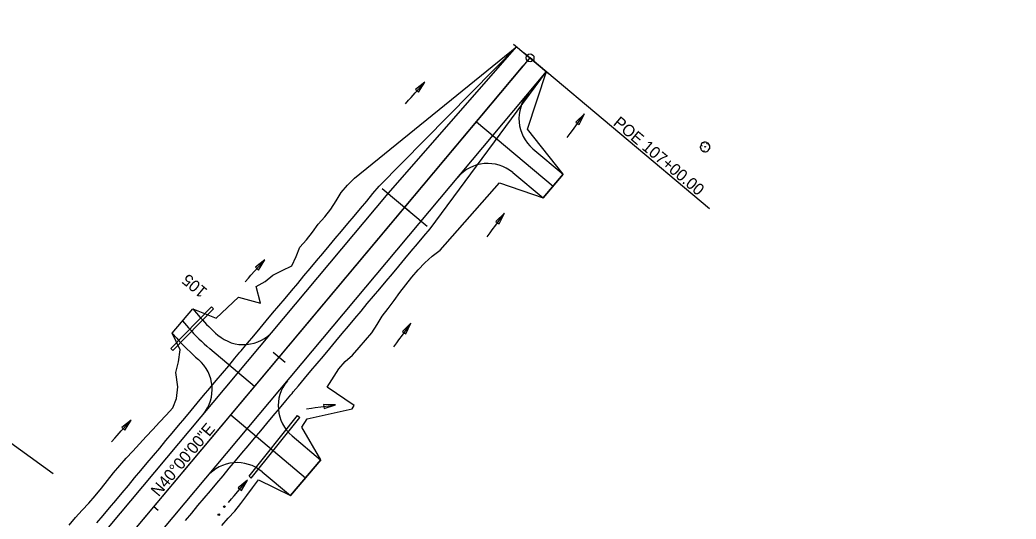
# Model space of a CAD drawing. Extents: x 1 to 1477871, y 1 to 1872901.
# Drawn here: x 1444024 to 1444534, y 1855060 to 1855316 of the extents above; entities that cross this region are included whole.
import ezdxf

# ---------------------------------------------------------------- set-up
doc = ezdxf.new("R2010")
doc.units = 0
for name, color, linetype in [('R_Drive', 7, 'Continuous'), ('R_Floodplain', 7, 'Continuous'), ('R_Horz Alg', 7, 'Continuous'), ('R_Horz Alg Annot', 7, 'Continuous'), ('R_No Plot', 7, 'Continuous'), ('R_Proposed Const Limits_Cut', 7, 'Continuous'), ('R_Proposed Const Limits_Fill', 7, 'Continuous'), ('R_Proposed Road_Lane', 7, 'Continuous'), ('R_Proposed Road_Shoulder', 7, 'Continuous'), ('R_Temp Easement', 7, 'Continuous'), ('R_Water', 7, 'Continuous'), ('S_TREE', 7, 'Continuous')]:
    doc.layers.add(name, color=color, linetype=linetype)

msp = doc.modelspace()

# ---------------------------------------------------------------- linework, layer by layer
at = {"layer": 'R_Drive'}
for p, q in [((1444286.64, 1855249.88), (1444302.16, 1855236.85)), ((1444276.36, 1855237.62), (1444291.84, 1855224.63)), ((1444302.2, 1855236.82), (1444291.84, 1855224.63)), ((1444101.85, 1855155.5), (1444112.32, 1855167.83)), ((1444112.32, 1855167.83), (1444116.19, 1855163.41)), ((1444101.85, 1855155.5), (1444104.16, 1855152.87)), ((1444163.28, 1855102.86), (1444177.88, 1855090.61)), ((1444177.94, 1855090.56), (1444162.4, 1855072.27)), ((1444147.86, 1855084.48), (1444162.4, 1855072.27))]:
    msp.add_line(p, q, dxfattribs=at)
for centre, radius, start, end in [((1444299.5, 1855265.2), 20, 140, 230), ((1444263.5, 1855222.3), 20, 50, 140), ((1444185.37, 1855224.07), 92, 221.2436, 229.1945), ((1444138.32, 1855169.57), 20, 229.1945, 320), ((1444185.37, 1855224.07), 108, 221.2436, 229.5469), ((1444102.32, 1855126.67), 20, 320, 49.5469), ((1444176.14, 1855118.18), 20, 140, 230), ((1444135, 1855069.16), 20, 50, 140)]:
    msp.add_arc(centre, radius, start, end, dxfattribs=at)
at = {"layer": 'R_Floodplain'}
msp.add_open_spline([(1444534.23, 1857777.84), (1444398.78, 1857609.12), (1444367.89, 1857131.47), (1444306.1, 1856808.28), (1444134.95, 1856378.26), (1444024.62, 1856227.92), (1443837.91, 1855964.82), (1443664.53, 1855852.06), (1443479.03, 1855867.82), (1443335.96, 1855886.01), (1443298.37, 1855854.49), (1443356.57, 1855756.28), (1443606.51, 1855482.27), (1443757.19, 1855307.33), (1443863.11, 1855113.58), (1443878.59, 1855007.91), (1443849.87, 1854910.07), (1443760.66, 1854753.08), (1443429.28, 1854512.04), (1443240.87, 1854371.16), (1443115.26, 1854254.04), (1443060.94, 1853889.1), (1443099.99, 1853680.31), (1443032.09, 1853386.66), (1443001.54, 1853198.25), (1444534.23, 1857777.84), (1443001.54, 1853198.25)], degree=3, dxfattribs=at)
at = {"layer": 'R_Horz Alg'}
for q in [(1444285.2, 1855296.38), (1444281.71, 1855292.23)]:
    msp.add_line((1444054.15, 1855021.02), q, dxfattribs=at)
at = {"layer": 'R_Horz Alg Annot'}
for points in [[(1444282.13, 1855298.95), (1444288.26, 1855293.81)], [(1444287.49, 1855294.45), (1444285.2, 1855296.38)], [(1444285.2, 1855296.38), (1444377.12, 1855219.25)], [(1444223.21, 1855217.85), (1444220.92, 1855219.78)], [(1444153.57, 1855145.74), (1444159.7, 1855140.6)], [(1444094.66, 1855064.64), (1444092.36, 1855066.57)]]:
    msp.add_lwpolyline(points, dxfattribs=at)
msp.add_circle((1444285.2, 1855296.38), 2, dxfattribs=at)
at = {"layer": 'R_No Plot'}
for p, q in [((1444276.77, 1855303.45), (1444294.69, 1855288.41)), ((1444257.75, 1855263.67), (1444297.02, 1855230.73)), ((1444209.43, 1855229.42), (1444232.41, 1855210.13)), ((1444107.09, 1855161.67), (1444110.18, 1855158.14)), ((1444144.06, 1855128.19), (1444121.09, 1855147.46)), ((1444131.82, 1855113.6), (1444170.17, 1855081.42))]:
    msp.add_line(p, q, dxfattribs=at)
msp.add_arc((1444185.37, 1855224.07), 100, 221.2436, 230, dxfattribs=at)
at = {"layer": 'R_Proposed Const Limits_Cut'}
for points in [[(1444112.32, 1855167.83), (1444124.29, 1855163.04), (1444135.72, 1855173.78), (1444147.11, 1855170.75), (1444144.76, 1855179.25), (1444149.49, 1855181.8), (1444153.3, 1855185.13), (1444158.22, 1855187.53), (1444163.17, 1855189.9), (1444165.33, 1855194.62), (1444167.24, 1855199.54), (1444170.62, 1855203.24), (1444173.68, 1855207.2), (1444176.6, 1855211.27), (1444179.99, 1855214.95), (1444183.14, 1855218.84), (1444185.78, 1855223.15), (1444188.45, 1855227.44), (1444191.68, 1855231.26), (1444195.24, 1855234.8), (1444278.35, 1855302.12)], [(1444195.05, 1855118.37), (1444181.28, 1855127.74), (1444187.14, 1855137.15), (1444190.52, 1855140.85), (1444194.26, 1855144.24), (1444197.54, 1855148.01), (1444200.81, 1855151.79), (1444204.06, 1855155.59), (1444206.78, 1855159.84), (1444209.48, 1855164.1), (1444212.53, 1855168.07), (1444215.48, 1855172.12), (1444218.43, 1855176.17), (1444221.53, 1855180.1), (1444224.55, 1855184.09), (1444227.85, 1855187.85), (1444231.32, 1855191.47), (1444235.06, 1855194.86), (1444239.2, 1855197.91), (1444269.48, 1855232.31), (1444291.84, 1855224.63), (1444302.2, 1855236.82), (1444283.94, 1855259.79), (1444293.62, 1855289.31)], [(1444102.11, 1855117.13), (1444104.09, 1855121.99), (1444104.7, 1855128.01), (1444103.75, 1855135.33), (1444105.08, 1855140.75), (1444105.86, 1855146.87), (1444101.85, 1855155.5)], [(1444127.17, 1855056.93), (1444130.5, 1855060.67), (1444133.88, 1855064.36), (1444137.04, 1855068.24), (1444140.03, 1855072.26), (1444143.02, 1855076.27), (1444146.01, 1855080.29), (1444162.4, 1855072.27), (1444177.94, 1855090.56), (1444168.24, 1855107.33), (1444170.99, 1855111.54), (1444193.99, 1855116.63), (1444195.05, 1855118.37)]]:
    msp.add_lwpolyline(points, dxfattribs=at)
at = {"layer": 'R_Proposed Const Limits_Fill'}
msp.add_lwpolyline([(1444049.04, 1855057.22), (1444052.28, 1855061.03), (1444055.65, 1855064.74), (1444059.08, 1855068.38), (1444062.38, 1855072.14), (1444065.51, 1855076.04), (1444068.63, 1855079.95), (1444071.75, 1855083.86), (1444074.98, 1855087.68), (1444078.27, 1855091.44), (1444081.72, 1855095.08), (1444085.09, 1855098.77), (1444088.46, 1855102.48), (1444091.85, 1855106.15), (1444095.27, 1855109.81), (1444098.68, 1855113.48), (1444102.11, 1855117.13)], dxfattribs=at)
at = {"layer": 'R_Proposed Road_Lane'}
for p, q in [((1444212.49, 1855226.85), (1444278.35, 1855302.12)), ((1444062.57, 1855013.95), (1444293.62, 1855289.31)), ((1444045.72, 1855028.1), (1444212.49, 1855226.85))]:
    msp.add_line(p, q, dxfattribs=at)
at = {"layer": 'R_Proposed Road_Shoulder'}
for p, q in [((1444207.89, 1855230.7), (1444278.35, 1855302.12)), ((1444233.94, 1855208.85), (1444293.62, 1855289.31))]:
    msp.add_line(p, q, dxfattribs=at)
for points in [[(1444063.27, 1855058.34), (1444066.48, 1855062.17), (1444069.69, 1855066), (1444072.91, 1855069.83), (1444076.12, 1855073.66), (1444079.34, 1855077.49), (1444082.55, 1855081.32), (1444085.76, 1855085.15), (1444088.98, 1855088.98), (1444092.19, 1855092.81), (1444095.41, 1855096.64), (1444098.62, 1855100.47), (1444101.83, 1855104.31), (1444105.05, 1855108.14), (1444108.26, 1855111.97), (1444111.48, 1855115.8), (1444114.69, 1855119.63), (1444117.9, 1855123.46), (1444121.12, 1855127.29), (1444124.33, 1855131.12), (1444127.55, 1855134.95), (1444130.76, 1855138.78), (1444133.97, 1855142.61), (1444136.54, 1855145.67), (1444137.19, 1855146.44), (1444137.83, 1855147.2), (1444140.4, 1855150.27), (1444143.62, 1855154.1), (1444146.83, 1855157.93), (1444150.04, 1855161.76), (1444153.26, 1855165.59), (1444156.47, 1855169.42), (1444159.68, 1855173.25), (1444162.9, 1855177.08), (1444166.11, 1855180.91), (1444169.33, 1855184.74), (1444172.54, 1855188.57), (1444175.75, 1855192.4), (1444178.97, 1855196.23), (1444182.18, 1855200.06), (1444185.4, 1855203.89), (1444188.61, 1855207.72), (1444191.82, 1855211.55), (1444195.04, 1855215.38), (1444198.25, 1855219.21), (1444201.47, 1855223.04), (1444204.68, 1855226.87), (1444207.89, 1855230.7)], [(1444108.6, 1855059.47), (1444111.81, 1855063.3), (1444115.02, 1855067.13), (1444118.24, 1855070.96), (1444121.45, 1855074.79), (1444124.67, 1855078.62), (1444127.88, 1855082.45), (1444131.09, 1855086.28), (1444134.31, 1855090.11), (1444137.52, 1855093.94), (1444140.74, 1855097.77), (1444143.95, 1855101.6), (1444147.16, 1855105.43), (1444150.38, 1855109.26), (1444153.59, 1855113.09), (1444156.8, 1855116.92), (1444160.02, 1855120.75), (1444162.59, 1855123.82), (1444163.23, 1855124.58), (1444163.88, 1855125.35), (1444166.45, 1855128.41), (1444169.66, 1855132.24), (1444172.87, 1855136.07), (1444176.09, 1855139.9), (1444179.3, 1855143.73), (1444182.52, 1855147.56), (1444185.73, 1855151.39), (1444188.94, 1855155.22), (1444192.16, 1855159.05), (1444195.37, 1855162.89), (1444198.59, 1855166.72), (1444201.8, 1855170.55), (1444205.01, 1855174.38), (1444208.23, 1855178.21), (1444211.44, 1855182.04), (1444214.66, 1855185.87), (1444217.87, 1855189.7), (1444221.08, 1855193.53), (1444224.3, 1855197.36), (1444227.51, 1855201.19), (1444230.73, 1855205.02), (1444233.94, 1855208.85)]]:
    msp.add_lwpolyline(points, dxfattribs=at)
at = {"layer": 'R_Temp Easement'}
msp.add_line((1443988.19, 1855121.34), (1444040.86, 1855083.67), dxfattribs=at)
at = {"layer": 'R_Water'}
for p, q in [((1444231.33, 1855283.97), (1444226.52, 1855280.22)), ((1444228.1, 1855278.8), (1444231.33, 1855283.97)), ((1444226.52, 1855280.22), (1444228.1, 1855278.8)), ((1444313.1, 1855267.7), (1444308.71, 1855263.48)), ((1444310.42, 1855262.23), (1444313.1, 1855267.7)), ((1444308.71, 1855263.48), (1444310.42, 1855262.23)), ((1444272.08, 1855216.82), (1444267.7, 1855212.59)), ((1444269.41, 1855211.34), (1444272.08, 1855216.82)), ((1444267.7, 1855212.59), (1444269.41, 1855211.34)), ((1444149.22, 1855192.93), (1444144.42, 1855189.18)), ((1444144.42, 1855189.18), (1444145.99, 1855187.76)), ((1444145.99, 1855187.76), (1444149.22, 1855192.93)), ((1444101.1, 1855147.55), (1444121.9, 1855168.88)), ((1444121.9, 1855168.88), (1444122.98, 1855167.84)), ((1444102.17, 1855146.51), (1444122.98, 1855167.84)), ((1444224.18, 1855160.54), (1444219.8, 1855156.32)), ((1444221.51, 1855155.07), (1444224.18, 1855160.54)), ((1444219.8, 1855156.32), (1444221.51, 1855155.07)), ((1444101.1, 1855147.55), (1444102.17, 1855146.51)), ((1444185.49, 1855118.7), (1444179.41, 1855118.96)), ((1444179.41, 1855118.96), (1444179.69, 1855116.87)), ((1444179.69, 1855116.87), (1444185.49, 1855118.7)), ((1444141.17, 1855082.19), (1444165.99, 1855113.23)), ((1444142.34, 1855081.25), (1444167.17, 1855112.29)), ((1444165.99, 1855113.23), (1444167.17, 1855112.29)), ((1444080.73, 1855110.97), (1444075.93, 1855107.22)), ((1444075.93, 1855107.22), (1444077.5, 1855105.8)), ((1444077.5, 1855105.8), (1444080.73, 1855110.97)), ((1444141.17, 1855082.19), (1444142.34, 1855081.25)), ((1444140.37, 1855080.14), (1444135.67, 1855076.27)), ((1444137.28, 1855074.89), (1444140.37, 1855080.14)), ((1444135.67, 1855076.27), (1444137.28, 1855074.89))]:
    msp.add_line(p, q, dxfattribs=at)
for points in [[(1444221.29, 1855272.82), (1444222.97, 1855274.69), (1444224.23, 1855276.09), (1444226.31, 1855278.4), (1444229.64, 1855282.1), (1444231.33, 1855283.97)], [(1444304.27, 1855255.58), (1444305.75, 1855257.61), (1444306.86, 1855259.14), (1444308.68, 1855261.64), (1444311.62, 1855265.67), (1444313.1, 1855267.7)], [(1444263.26, 1855204.69), (1444264.74, 1855206.73), (1444265.85, 1855208.25), (1444267.67, 1855210.76), (1444270.6, 1855214.78), (1444272.08, 1855216.82)], [(1444139.19, 1855181.78), (1444140.87, 1855183.65), (1444142.13, 1855185.05), (1444144.2, 1855187.36), (1444147.54, 1855191.06), (1444149.22, 1855192.92)], [(1444215.36, 1855148.41), (1444216.84, 1855150.45), (1444217.95, 1855151.97), (1444219.77, 1855154.48), (1444222.7, 1855158.51), (1444224.19, 1855160.54)], [(1444170.63, 1855116.73), (1444173.12, 1855117.06), (1444174.99, 1855117.31), (1444178.06, 1855117.72), (1444183, 1855118.37), (1444185.49, 1855118.7)], [(1444070.69, 1855099.82), (1444072.37, 1855101.69), (1444073.63, 1855103.09), (1444075.71, 1855105.4), (1444079.05, 1855109.1), (1444080.73, 1855110.97)], [(1444130.63, 1855068.74), (1444132.26, 1855070.65), (1444133.49, 1855072.08), (1444135.5, 1855074.44), (1444138.74, 1855078.23), (1444140.38, 1855080.14)]]:
    msp.add_lwpolyline(points, dxfattribs=at)
for centre in [(1444128.56, 1855066.64), (1444125.71, 1855062.52)]:
    msp.add_circle(centre, 0.375, dxfattribs=at)
at = {"layer": 'S_TREE'}
for p, q in [((1444372.67, 1855250.06), (1444373, 1855250.16)), ((1444372.93, 1855251.45), (1444373.32, 1855251.26)), ((1444374.11, 1855253.11), (1444374.31, 1855252.69)), ((1444375.94, 1855252.75), (1444375.62, 1855252.22)), ((1444376.85, 1855251.78), (1444376.44, 1855251.7)), ((1444374.39, 1855248.52), (1444374.45, 1855248.91)), ((1444376.72, 1855249.41), (1444376.43, 1855249.83))]:
    msp.add_line(p, q, dxfattribs=at)
msp.add_circle((1444374.88, 1855250.88), 0.188, dxfattribs=at)
for centre, major_axis, ratio, start_param, end_param in [((1444372.82, 1855250.74), (-0.093, -0.647), 0.711534, 3.141592, 6.283185), ((1444373.58, 1855249.3), (0.833, -0.798), 0.482994, 3.141593, 6.283185), ((1444373.53, 1855252.22), (0.614, 0.81), 0.529943, 0, 3.141593), ((1444375.07, 1855252.87), (0.928, -0.167), 0.420543, 6.283185, 9.424777), ((1444376.41, 1855252.26), (0.398, -0.437), 0.646762, 0, 3.141593), ((1444376.77, 1855250.6), (-0.02, -1.19), 0.471018, 0, 3.141593), ((1444375.58, 1855248.97), (1.16, 0.47), 0.405113, 3.141593, 6.283186)]:
    msp.add_ellipse(centre, major_axis=major_axis, ratio=ratio, start_param=start_param, end_param=end_param, dxfattribs=at)

# ---------------------------------------------------------------- texts
at = {"layer": 'R_Horz Alg Annot'}
for s, rotation, p in [('POE 107+00.00', 320, (1444327.35, 1855262.31)), ('105', 140, (1444120.26, 1855177.61)), ('N40%%d00\'00"E', 50, (1444094.89, 1855071.36))]:
    msp.add_text(s, height=6, rotation=rotation, dxfattribs=at).set_placement(p)

doc.saveas('drawing.dxf')
